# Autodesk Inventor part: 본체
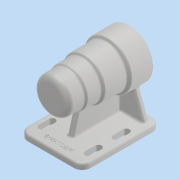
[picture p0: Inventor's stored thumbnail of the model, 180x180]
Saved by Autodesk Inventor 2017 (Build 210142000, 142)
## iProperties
Part Number: 본체
Material: 알루미늄 6061
Document SubType Name: Modeling
Designer: MRC
Density: 2.7 g/cm^3
Appearance: 알루미늄 - 평지
Mass: 691.322 g
Surface Area: 698.567 cm^2
Volume: 256.045 cm^3
Author: MRC
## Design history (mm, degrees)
sketch "스케치1"
  geometry: C1 r 34 at (0, 0); 1 further point
  constraints: 1 centre point, 1 coincident
  dimensions: "d0" = 68 diameter of C1
extrude "돌출1" new body sketch "스케치1" distance "d1" = 32; taper "d2" = 0 deg
sketch "스케치2"
  geometry: C1 r 34 at (0, 0) reference; C2 r 30 at (0, 0)
  constraints: 1 centre point, 1 coincident
  dimensions: "d3" = 60 diameter of C2
extrude "돌출2" join sketch "스케치2" distance "d4" = 34; taper "d5" = 0 deg
sketch "스케치3"
  geometry: C1 r 30 at (0, 0) reference; C2 r 27 at (0, 0)
  constraints: 1 centre point, 1 coincident
  dimensions: "d6" = 54 diameter of C2
extrude "돌출3" join sketch "스케치3" distance "d7" = 22; taper "d8" = 0 deg
sketch "스케치4"
  geometry: C1 r 27 at (0, 0) reference; C2 r 25 at (0, 0)
  constraints: 1 centre point, 1 coincident
  dimensions: "d9" = 50 diameter of C2
extrude "돌출4" join sketch "스케치4" distance "d10" = 24; taper "d11" = 0 deg
sketch "스케치5"
  geometry: L1 (0, 0)-(21, 0); L2 (21, 0)-(21, -15); L3 (21, -15)-(0, -15); L4 (0, -15)-(0, 0); L5 (0, -15)-(24, -15); L6 (24, -15)-(24, -69); L7 (24, -69)-(0, -69); L8 (0, -69)-(0, -15); L9 (0, -69)-(21, -69); L10 (21, -69)-(21, -81); L11 (21, -81)-(0, -81); L12 (0, -81)-(0, -69); L13 (0, -81)-(17.5, -81); L14 (17.5, -81)-(17.5, -99); L15 (17.5, -99)-(0, -99); L16 (0, -99)-(0, -81); L17 (0, -99)-(16, -99); L18 (16, -99)-(16, -103); L19 (16, -103)-(0, -103); L20 (0, -103)-(0, -99); L21 (0, -103)-(12.605, -103); L22 (-25, -112)-(25, -112) reference; L23 (0, -103)-(10.5, -103); L24 (10.5, -103)-(10.5, -106); L25 (10.5, -106)-(0, -106); L26 (0, -106)-(0, -103)
  constraints: 50 end point, 12 parallel, 7 horizontal, 6 perpendicular, 1 point on line
  dimensions: "d12" = 15 distance of L1.end L2.end; "d13" = 54 distance of L5.end L6.end; "d14" = 12 distance of L9.end L10.end; "d15" = 18 distance of L13.end L14.end; "d16" = 4 distance of L17.end L18.end; "d17" = 3 distance of L23.end L24.end; "d18" = 42 diameter of L2 L4; "d19" = 48 diameter of L6 L8; "d20" = 35 diameter of L14 L16; "d21" = 32 diameter of L18 L20; "d22" = 21 diameter of L24 L26
revolve "회전1" sketch "스케치5" stored, may be unused: angle "d23" = 90 deg
chamfer "모따기1" distance "d24" = 1; stored, may be unused: second distance "d25" = 2, angle "d26" = 45 deg
fillet "모깎기1" dims "d27" = 3
fillet "모깎기2" dims "d28" = 0.3
sketch "스케치6"
  geometry: C1 r 34 at (0, 0) reference; 1 further point
  constraints: 1 horizontal alignment
  dimensions: "d29" = 26 distance of C1.centre point (-26, 0)
hole "구멍1" sketch "스케치6" at (-26, 0) diameter "d30" = 3.242; stored, may be unused: countersink angle "d34" = 90 deg, drill point angle "d36" = 118 deg; dims "d31" = 8, "d32" = 4, "d33" = 2, "d35" = 11
node "작업 평면1"
sketch "스케치7"
  geometry: L1 (-45, -112)-(45, -112); L2 (45, -112)-(45, 0); L3 (45, 0)-(-45, 0); L4 (-45, 0)-(-45, -112); 2 further points
  constraints: 8 end point, 2 coincident, 2 parallel, 1 horizontal, 1 midpoint, 1 perpendicular
  dimensions: "d41" = 112 distance of L3.end L1.start; "d42" = 90 distance of L1.start L1.end
extrude "돌출5" join sketch "스케치7" distance "d43" = 8; taper "d44" = 0 deg
sketch "스케치8"
  geometry: L1 (33, 92)-(33, 77); L2 (28.5, 92)-(28.5, 77); L3 (37.5, 77)-(37.5, 92); L4 (33, 52)-(33, 37); L5 (28.5, 52)-(28.5, 37); L6 (37.5, 37)-(37.5, 52); L7 (45, 112)-(-45, 112) reference; A1 r 4.5 centre (33, 92) between (37.5, 92) and (28.5, 92); A2 r 4.5 centre (33, 77) between (28.5, 77) and (37.5, 77); A3 r 4.5 centre (33, 52) between (37.5, 52) and (28.5, 52); A4 r 4.5 centre (33, 37) between (28.5, 37) and (37.5, 37); 3 further points
  constraints: 16 end point, 8 point on circle, 8 tangent, 4 centre point, 2 midpoint, 2 parallel, 2 vertical, 1 vertical alignment
  dimensions: "d45" = 15 distance of L1.start L1.end; "d46" = 9 diameter of A2; "d48" = 33 horizontal distance of point (0, 0) point (33, 84.5); "d49" = 15 distance of L4.start L4.end; "d50" = 9 diameter of A4; "d51" = 25 distance of L4.start L1.end; "d87" = 20 distance from line of L1.start L7
extrude "돌출6" cut sketch "스케치8" stored distance "d52" = 8; taper "d53" = 0 deg
fillet "모깎기3" dims "d54" = 12
fillet "모깎기4" dims "d55" = 3
fillet "모깎기5" dims "d56" = 8
fillet "모깎기6" dims "d57" = 3
node "작업 평면2"
sketch "스케치11"
  geometry: L1 (4, 85)-(-4, 85); L2 (-4, 85)-(-4, 8); L3 (4, 8)-(4, 85); L4 (45, 12)-(45, 100) reference; L5 (-4, 8)-(4, 8); L6 (-33, 0)-(33, 0) reference; 4 further points
  constraints: 8 end point, 2 horizontal, 2 vertical alignment, 1 coincident, 1 midpoint, 1 parallel, 1 perpendicular
  dimensions: "d66" = 8 distance of L1.start L1.end; "d74" = 8 distance between parallel lines of L6 L5; "d75" = 77 distance from line of point (0, 8) L1
extrude "돌출7" join sketch "스케치11" stored distance "d68" = 8; taper "d69" = 0 deg
feature "면 기울기1" dims angle "d70" = 15 deg
node "작업 평면3"
sketch "스케치12"
  geometry: L1 (-31.663, -47.336)-(-37, -62); L2 (-42, -62)-(-33, -62) reference; L3 (-45, -65)-(-45, -70) reference; 1 further point
  constraints: 2 end point, 1 point on line
  dimensions: "d72" = 110 deg angle of L2 L1; "d73" = 8 distance from line of L3 L1.end
feature "리브1" sketch "스케치12" dims "d76" = 33, "d77" = 8, "d78" = 0, "d79" = 0, "d80" = 1, "d81" = 1
fillet "모깎기7" dims "d82" = 3
fillet "모깎기8" dims "d83" = 3
sketch "스케치13"
  geometry: L1 (-33, 109)-(33, 109) reference; L2 (33, 112)-(-33, 112) reference; 3 further points
  constraints: 1 midpoint, 1 vertical alignment, 1 other
  dimensions: "d84" = 12 distance from line of L2 point (0, 100)
feature "엠보싱1" sketch "스케치13" dims "d85" = 0.5, "d86" = 0
node "솔리드1"
pattern_circular "원형 패턴1" dims angle "d38" = 360 deg
mirror "미러1"
mirror "미러2"
other parameters: "d58" = -8, "d71" = -8
